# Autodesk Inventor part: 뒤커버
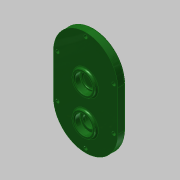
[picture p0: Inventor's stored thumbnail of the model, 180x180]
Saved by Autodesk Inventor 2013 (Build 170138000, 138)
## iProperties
Created: 2016-12
Part Number: 뒤커버
Material: 일반
Document SubType Name: Modeling
Designer: mduedu
Density: 1 g/cm^3
Author: mduedu
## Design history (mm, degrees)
sketch "스케치1"
  geometry: L1 (40, -25)-(40, 25); L2 (-40, 25)-(-40, -25); L3 (-40, -25)-(40, 25); L4 (40, -25)-(-40, 25); A1 r 40 centre (0, 25) between (40, 25) and (-40, 25); A2 r 40 centre (0, -25) between (-40, -25) and (40, -25); 1 further point
  constraints: 8 end point, 4 point on circle, 4 tangent, 2 centre point, 2 midpoint, 1 parallel, 1 vertical
  dimensions: "d0" = 130 dimension on A2 A1; "d2" = 80 distance between parallel lines of L1 L2
extrude "돌출1" new body sketch "스케치1" distance "d3" = 10; taper "d4" = 0 deg
sketch "스케치2"
  geometry: C1 r 14 at (0, 11); 1 further point
  constraints: 1 centre point, 1 vertical alignment
  dimensions: "d5" = 28 diameter of C1; "d6" = 11 distance of C1.centre point (0, 0)
extrude "돌출2" join sketch "스케치2" distance "d7" = 3; taper "d8" = 0 deg
sketch "스케치3"
  geometry: C1 r 14 at (0, -33.1); C2 r 14 at (0, 11) reference; 1 further point
  constraints: 1 centre point, 1 vertical alignment
  dimensions: "d9" = 28 diameter of C1; "d69" = 44.1 distance of C1.centre C2.centre
extrude "돌출3" join sketch "스케치3" distance "d11" = 3; taper "d12" = 0 deg
hole "구멍1" diameter "d15" = 22; stored, may be unused: countersink angle "d19" = 90 deg, drill point angle "d21" = 0 deg; dims "d13" = 10, "d14" = 10, "d16" = 6, "d17" = 4, "d18" = 2, "d20" = 7
hole "구멍2" diameter "d24" = 18; stored, may be unused: countersink angle "d28" = 90 deg, drill point angle "d30" = 0 deg; dims "d22" = 10, "d23" = 10, "d25" = 6, "d26" = 4, "d27" = 2, "d29" = 1
hole "구멍3" diameter "d33" = 22; stored, may be unused: countersink angle "d37" = 90 deg, drill point angle "d39" = 0 deg; dims "d31" = 10, "d32" = 10, "d34" = 6, "d35" = 4, "d36" = 2, "d38" = 7
sketch "스케치4"
  geometry: C1 r 14 at (0, -33.1) reference; C2 r 18 at (0, -33.1); 1 further point
  constraints: 1 centre point, 1 coincident
  dimensions: "d40" = 36 diameter of C2
extrude "돌출4" join sketch "스케치4" distance "d41" = 4; taper "d42" = 0 deg
hole "구멍4" diameter "d45" = 22; stored, may be unused: countersink angle "d49" = 90 deg, drill point angle "d51" = 0 deg; dims "d46" = 6, "d47" = 4, "d48" = 2, "d50" = 7.3, "d80" = 10, "d81" = 10
hole "구멍5" diameter "d54" = 15; stored, may be unused: countersink angle "d58" = 90 deg, drill point angle "d60" = 0 deg; dims "d52" = 10, "d53" = 10, "d55" = 6, "d56" = 4, "d57" = 2, "d59" = 7
fillet "모깎기1" dims "d61" = 0.3
fillet "모깎기2" dims "d62" = 2
chamfer "모따기1" distance "d63" = 1; stored, may be unused: second distance "d64" = 2, angle "d65" = 45 deg
chamfer "모따기2" distance "d82" = 0.7; stored, may be unused: second distance "d83" = 2, angle "d84" = 30 deg
fillet "모깎기3" dims "d66" = 2
fillet "모깎기4" dims "d67" = 2
fillet "모깎기5" dims "d68" = 2
sketch "스케치5"
  geometry: L1 (-40, 25)-(-40, -25) reference; L2 (40, -25)-(40, 25) reference; L3 (35, 25)-(35, -25); L4 (-35, -25)-(-35, 25); A1 r 40 centre (0, 25) between (40, 25) and (-40, 25) reference; A2 r 40 centre (0, -25) between (-40, -25) and (40, -25) reference; A3 r 35 centre (0, 25) between (35, 25) and (-35, 25); A4 r 35 centre (0, -25) between (-35, -25) and (35, -25); 2 further points
  constraints: 5 point on circle, 4 end point, 2 centre point, 1 vertical alignment, 3 other
  dimensions: "d70" = 5 distance between parallel lines of L2 L3
sketch "스케치6"
  geometry: 1 further point
  constraints: 1 other
hole "구멍6" sketch "스케치6" at (0, 60) diameter "d71" = 4.5; stored, may be unused: countersink angle "d75" = 90 deg, drill point angle "d77" = 0 deg; dims "d72" = 6, "d73" = 8, "d74" = 4.6, "d76" = 8
node "솔리드1"
pattern_linear "직사각형 패턴1"
